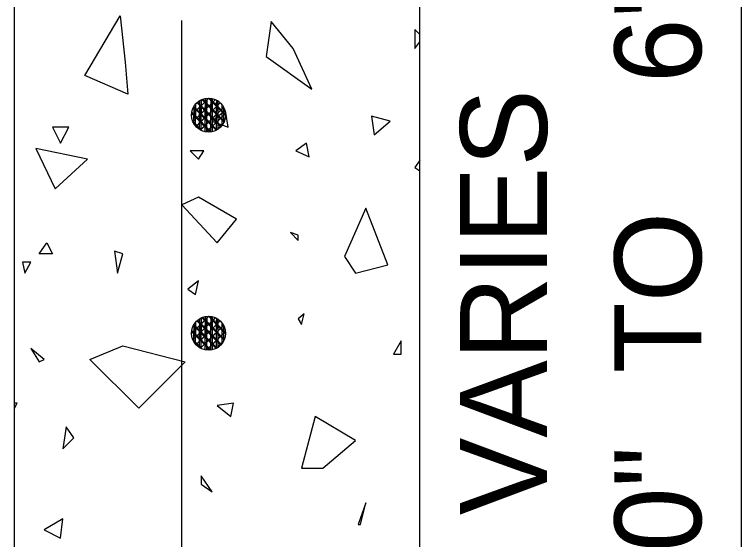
# Model space of a CAD drawing. Extents: x 8.6 to 15.9, y 6.4 to 16.6.
# Drawn here: x 11.677 to 12.179, y 12.084 to 12.447 of the extents above; entities that cross this region are included whole.
import ezdxf

# ---------------------------------------------------------------- set-up
doc = ezdxf.new("R2010")
doc.units = 0
for name, color, linetype in [('DETL-DIMS', 7, 'Continuous'), ('DETL-LINE', 7, 'Continuous'), ('DETL-NOTE', 7, 'Continuous'), ('DETL-PATT', 7, 'Continuous')]:
    doc.layers.add(name, color=color, linetype=linetype)

msp = doc.modelspace()

# ---------------------------------------------------------------- linework, layer by layer
at = {"layer": 'DETL-DIMS'}
msp.add_line((12.17919, 11.92421), (12.17919, 12.60906), dxfattribs=at)
at = {"layer": 'DETL-LINE'}
for p, q in [((11.95697, 9.51644), (11.95697, 12.84203)), ((11.67679, 9.84944), (11.67679, 12.60906)), ((11.79234, 11.96892), (11.79234, 12.44273)), ((11.8096, 12.38747), (11.80071, 12.37873)), ((11.81231, 12.38469), (11.80338, 12.37595)), ((11.80471, 12.37373), (11.80482, 12.38621)), ((11.81379, 12.37547), (11.80505, 12.38436)), ((11.80582, 12.37373), (11.80594, 12.38621)), ((11.81508, 12.38744), (11.80616, 12.37869)), ((11.81627, 12.37777), (11.80753, 12.38666)), ((11.81657, 12.37821), (11.80779, 12.3871)), ((11.8086, 12.37369), (11.80871, 12.38618)), ((11.81779, 12.38466), (11.8089, 12.37592)), ((11.80971, 12.37369), (11.80979, 12.38618)), ((11.81249, 12.37366), (11.8126, 12.38614)), ((11.82179, 12.37773), (11.81305, 12.38662)), ((11.82205, 12.37814), (11.81331, 12.38703)), ((11.8136, 12.37366), (11.81368, 12.38614)), ((11.81638, 12.37362), (11.81649, 12.3861)), ((11.81745, 12.37362), (11.81757, 12.3861)), ((11.80953, 12.38195), (11.80064, 12.37321)), ((11.8019, 12.36988), (11.80201, 12.38236)), ((11.81071, 12.37232), (11.80197, 12.38125)), ((11.81101, 12.37273), (11.80227, 12.38162)), ((11.80468, 12.36984), (11.80479, 12.38232)), ((11.81349, 12.37506), (11.80475, 12.38395)), ((11.80579, 12.36984), (11.8059, 12.38232)), ((11.81505, 12.38192), (11.80612, 12.37318)), ((11.81623, 12.37229), (11.80749, 12.38121)), ((11.81653, 12.37269), (11.80775, 12.38158)), ((11.80857, 12.36981), (11.80868, 12.38229)), ((11.80968, 12.36981), (11.80979, 12.38229)), ((11.81901, 12.37499), (11.81027, 12.38388)), ((11.81931, 12.37544), (11.81053, 12.38432)), ((11.82053, 12.38188), (11.81164, 12.37314)), ((11.81245, 12.36977), (11.81257, 12.38225)), ((11.81357, 12.36977), (11.81368, 12.38225)), ((11.81634, 12.36977), (11.81645, 12.38221)), ((11.81745, 12.36973), (11.81757, 12.38221)), ((11.80797, 12.36962), (11.79919, 12.37851)), ((11.80823, 12.37003), (11.79949, 12.37892)), ((11.81068, 12.36684), (11.80194, 12.37573)), ((11.81097, 12.36725), (11.80223, 12.37618)), ((11.81227, 12.37921), (11.80334, 12.37044)), ((11.81345, 12.36958), (11.80471, 12.37847)), ((11.81375, 12.36995), (11.80501, 12.37884)), ((11.81501, 12.37644), (11.80608, 12.36766)), ((11.81619, 12.36681), (11.80745, 12.37569)), ((11.81649, 12.36718), (11.80771, 12.3761)), ((11.80853, 12.36592), (11.80864, 12.3784)), ((11.81775, 12.37918), (11.80886, 12.3704)), ((11.80964, 12.36592), (11.80975, 12.3784)), ((11.81897, 12.36955), (11.81023, 12.37844)), ((11.81927, 12.36992), (11.81049, 12.37881)), ((11.82049, 12.3764), (11.8116, 12.36762)), ((11.81242, 12.36588), (11.81253, 12.37836)), ((11.81353, 12.36588), (11.81364, 12.37836)), ((11.8096, 12.23677), (11.80071, 12.22803)), ((11.81231, 12.23399), (11.80338, 12.22525)), ((11.80471, 12.22303), (11.80482, 12.23551)), ((11.81379, 12.22477), (11.80505, 12.23366)), ((11.80582, 12.22303), (11.80594, 12.23551)), ((11.81508, 12.23673), (11.80616, 12.22799)), ((11.81627, 12.22706), (11.80753, 12.23595)), ((11.81657, 12.22751), (11.80779, 12.2364)), ((11.8086, 12.22299), (11.80871, 12.23547)), ((11.81779, 12.23395), (11.8089, 12.22521)), ((11.80971, 12.22299), (11.80979, 12.23547)), ((11.81931, 12.22473), (11.81053, 12.23362)), ((11.81249, 12.22295), (11.8126, 12.23544)), ((11.82179, 12.22703), (11.81305, 12.23592)), ((11.82205, 12.22744), (11.81331, 12.23632)), ((11.8136, 12.22295), (11.81368, 12.23544)), ((11.81638, 12.22292), (11.81649, 12.2354)), ((11.81745, 12.22292), (11.81757, 12.2354)), ((11.80953, 12.23125), (11.80064, 12.22251)), ((11.8019, 12.21918), (11.80201, 12.23166)), ((11.81071, 12.22162), (11.80197, 12.23055)), ((11.81101, 12.22203), (11.80227, 12.23092)), ((11.80468, 12.21914), (11.80479, 12.23162)), ((11.81349, 12.22436), (11.80475, 12.23325)), ((11.80579, 12.21914), (11.8059, 12.23162)), ((11.81505, 12.23121), (11.80612, 12.22247)), ((11.81623, 12.22158), (11.80749, 12.23051)), ((11.81653, 12.22199), (11.80775, 12.23088)), ((11.80857, 12.2191), (11.80868, 12.23158)), ((11.80968, 12.2191), (11.80979, 12.23158)), ((11.81901, 12.22429), (11.81027, 12.23318)), ((11.82053, 12.23118), (11.81164, 12.22244)), ((11.81245, 12.21906), (11.81257, 12.23155)), ((11.81357, 12.21906), (11.81368, 12.23155)), ((11.81634, 12.21906), (11.81645, 12.23151)), ((11.81745, 12.21903), (11.81757, 12.23151)), ((11.80797, 12.21892), (11.79919, 12.22781)), ((11.80823, 12.21932), (11.79949, 12.22821)), ((11.81068, 12.21614), (11.80194, 12.22503)), ((11.81097, 12.21655), (11.80223, 12.22547)), ((11.81227, 12.22851), (11.80334, 12.21973)), ((11.81345, 12.21888), (11.80471, 12.22777)), ((11.81375, 12.21925), (11.80501, 12.22814)), ((11.81501, 12.22573), (11.80608, 12.21695)), ((11.81619, 12.2161), (11.80745, 12.22499)), ((11.81649, 12.21647), (11.80771, 12.2254)), ((11.80853, 12.21521), (11.80864, 12.22769)), ((11.81775, 12.22847), (11.80886, 12.21969)), ((11.80964, 12.21521), (11.80975, 12.22769)), ((11.81897, 12.21884), (11.81023, 12.22773)), ((11.81927, 12.21921), (11.81049, 12.2281)), ((11.82049, 12.22569), (11.8116, 12.21692)), ((11.81242, 12.21518), (11.81253, 12.22766)), ((11.81353, 12.21518), (11.81364, 12.22766))]:
    msp.add_line(p, q, dxfattribs=at)
for points in [[(11.80682, 12.38473), (11.79912, 12.37718)], [(11.80194, 12.37377), (11.80201, 12.38499)], [(11.80197, 12.37766), (11.80201, 12.38499)], [(11.80197, 12.38155), (11.80201, 12.38499)], [(11.81079, 12.37784), (11.80286, 12.38588)], [(11.80808, 12.38062), (11.80286, 12.38588)], [(11.80534, 12.3834), (11.80286, 12.38588)], [(11.81105, 12.37825), (11.80327, 12.38618)], [(11.80834, 12.38103), (11.80327, 12.38618)], [(11.8056, 12.38381), (11.80327, 12.38618)], [(11.81112, 12.38899), (11.80345, 12.38147)], [(11.80475, 12.37762), (11.80482, 12.38732)], [(11.80479, 12.38151), (11.80482, 12.38732)], [(11.80482, 12.3854), (11.80482, 12.38732)], [(11.80582, 12.37762), (11.80594, 12.38792)], [(11.80586, 12.38151), (11.80594, 12.38792)], [(11.8059, 12.3854), (11.80594, 12.38792)], [(11.81112, 12.38899), (11.80623, 12.38418)], [(11.81357, 12.38055), (11.80623, 12.38803)], [(11.81082, 12.38332), (11.80623, 12.38803)], [(11.80812, 12.3861), (11.80623, 12.38803)], [(11.81382, 12.38099), (11.80671, 12.38825)], [(11.81112, 12.38377), (11.80671, 12.38825)], [(11.80838, 12.38651), (11.80671, 12.38825)], [(11.80864, 12.37758), (11.80871, 12.38881)], [(11.80868, 12.38147), (11.80871, 12.38881)], [(11.80871, 12.38536), (11.80871, 12.38881)], [(11.81564, 12.38795), (11.80894, 12.3814)], [(11.80971, 12.37758), (11.80982, 12.38895)], [(11.80975, 12.38147), (11.80982, 12.38895)], [(11.80979, 12.38536), (11.80982, 12.38895)], [(11.81905, 12.38051), (11.81075, 12.38899)], [(11.81634, 12.38329), (11.81075, 12.38899)], [(11.8136, 12.38606), (11.81075, 12.38899)], [(11.81086, 12.38884), (11.81075, 12.38899)], [(11.81934, 12.38092), (11.81142, 12.38899)], [(11.8166, 12.38369), (11.81142, 12.38899)], [(11.8139, 12.38647), (11.81142, 12.38899)], [(11.81894, 12.38577), (11.81168, 12.37862)], [(11.81253, 12.37755), (11.8126, 12.38884)], [(11.81257, 12.38144), (11.8126, 12.38884)], [(11.8126, 12.38532), (11.8126, 12.38884)], [(11.8136, 12.37755), (11.81371, 12.38862)], [(11.81364, 12.38144), (11.81371, 12.38862)], [(11.81368, 12.38532), (11.81371, 12.38862)], [(11.81642, 12.37751), (11.81649, 12.38755)], [(11.81645, 12.3814), (11.81649, 12.38755)], [(11.81645, 12.38529), (11.81649, 12.38755)], [(11.81749, 12.37751), (11.8176, 12.38688)], [(11.81753, 12.3814), (11.8176, 12.38688)], [(11.81757, 12.38529), (11.8176, 12.38688)], [(11.80405, 12.38199), (11.79912, 12.37718)], [(11.80127, 12.37932), (11.79912, 12.37718)], [(11.80801, 12.3751), (11.80049, 12.38277)], [(11.80531, 12.37788), (11.80049, 12.38277)], [(11.80257, 12.38066), (11.80049, 12.38277)], [(11.80827, 12.37551), (11.80075, 12.38321)], [(11.80557, 12.37829), (11.80075, 12.38321)], [(11.80282, 12.38106), (11.80075, 12.38321)], [(11.80079, 12.37121), (11.8009, 12.38236)], [(11.80082, 12.37377), (11.8009, 12.38347)], [(11.80086, 12.37766), (11.8009, 12.38347)], [(11.8009, 12.38155), (11.8009, 12.38347)], [(11.82157, 12.3724), (11.81301, 12.38114)], [(11.82179, 12.37292), (11.81327, 12.38155)], [(11.82131, 12.38262), (11.81442, 12.37584)], [(11.8226, 12.37692), (11.81575, 12.38384)], [(11.8226, 12.37758), (11.81605, 12.38425)], [(11.8226, 12.37692), (11.81849, 12.3811)], [(11.8226, 12.37758), (11.81879, 12.38147)], [(11.82023, 12.37018), (11.82034, 12.38218)], [(11.82027, 12.37362), (11.82034, 12.38418)], [(11.82031, 12.37751), (11.82034, 12.38418)], [(11.82034, 12.3814), (11.82034, 12.38418)], [(11.82134, 12.37358), (11.82145, 12.38236)], [(11.82134, 12.37192), (11.82142, 12.38218)], [(11.82138, 12.37747), (11.82145, 12.38236)], [(11.82142, 12.38136), (11.82145, 12.38236)], [(11.80523, 12.37236), (11.79919, 12.37851)], [(11.80253, 12.37514), (11.79919, 12.37851)], [(11.79979, 12.37792), (11.79919, 12.37851)], [(11.80549, 12.37281), (11.79927, 12.37918)], [(11.80279, 12.37558), (11.79927, 12.37918)], [(11.80008, 12.37836), (11.79927, 12.37918)], [(11.80675, 12.37925), (11.80005, 12.37266)], [(11.80397, 12.37655), (11.80005, 12.37266)], [(11.80079, 12.37121), (11.80086, 12.37847)], [(11.80079, 12.37121), (11.80082, 12.37458)], [(11.8019, 12.36969), (11.80197, 12.37847)], [(11.8019, 12.36969), (11.80194, 12.37458)], [(11.80949, 12.37647), (11.80219, 12.36932)], [(11.80464, 12.36729), (11.80475, 12.37844)], [(11.80464, 12.36729), (11.80471, 12.37455)], [(11.80575, 12.36666), (11.80586, 12.37844)], [(11.80575, 12.36666), (11.80582, 12.37455)], [(11.80853, 12.36573), (11.8086, 12.37451)], [(11.80964, 12.36555), (11.80971, 12.37451)], [(11.81242, 12.36562), (11.81249, 12.37447)], [(11.81938, 12.3691), (11.81294, 12.37566)], [(11.81968, 12.36951), (11.81323, 12.37606)], [(11.81353, 12.36581), (11.8136, 12.37447)], [(11.82253, 12.3784), (11.81438, 12.37036)], [(11.82157, 12.3724), (11.81571, 12.37836)], [(11.82179, 12.37292), (11.81601, 12.37877)], [(11.81631, 12.36684), (11.81642, 12.37832)], [(11.81631, 12.36684), (11.81638, 12.37444)], [(11.82253, 12.3784), (11.81716, 12.37306)], [(11.81742, 12.36751), (11.81753, 12.37832)], [(11.81742, 12.36751), (11.81749, 12.37444)], [(11.82023, 12.37018), (11.82031, 12.37829)], [(11.82023, 12.37018), (11.82027, 12.3744)], [(11.82134, 12.37192), (11.82142, 12.37829)], [(11.82134, 12.37192), (11.82138, 12.3744)], [(11.80634, 12.3664), (11.79994, 12.37295)], [(11.80545, 12.36729), (11.79994, 12.37295)], [(11.80271, 12.37006), (11.79994, 12.37295)], [(11.80005, 12.37284), (11.79994, 12.37295)], [(11.80119, 12.37381), (11.80005, 12.37266)], [(11.80508, 12.36699), (11.80053, 12.37162)], [(11.80508, 12.36699), (11.80053, 12.37162)], [(11.80245, 12.36969), (11.80053, 12.37162)], [(11.80508, 12.36699), (11.8019, 12.37025)], [(11.80671, 12.37377), (11.80219, 12.36932)], [(11.80394, 12.37103), (11.80219, 12.36932)], [(11.80634, 12.3664), (11.80219, 12.37066)], [(11.81197, 12.36555), (11.80468, 12.37295)], [(11.81253, 12.36562), (11.80497, 12.3734)], [(11.81223, 12.37369), (11.80531, 12.36688)], [(11.80945, 12.37099), (11.80531, 12.36688)], [(11.81197, 12.36555), (11.80738, 12.37018)], [(11.81253, 12.36562), (11.80768, 12.37062)], [(11.81771, 12.37366), (11.80949, 12.36558)], [(11.81494, 12.37092), (11.80949, 12.36558)], [(11.81623, 12.36677), (11.81016, 12.37292)], [(11.81664, 12.36703), (11.81045, 12.37332)], [(11.82119, 12.37162), (11.81631, 12.36681)], [(11.82042, 12.37088), (11.81631, 12.36681)], [(11.82119, 12.37162), (11.81708, 12.36758)], [(11.82119, 12.37162), (11.81986, 12.37029)], [(11.80508, 12.36699), (11.8046, 12.36747)], [(11.80634, 12.3664), (11.8049, 12.36788)], [(11.80668, 12.36825), (11.80531, 12.36688)], [(11.81216, 12.36821), (11.80949, 12.36558)], [(11.81764, 12.36814), (11.81631, 12.36681)], [(11.80682, 12.23403), (11.79912, 12.22647)], [(11.80194, 12.22306), (11.80201, 12.23429)], [(11.80197, 12.22695), (11.80201, 12.23429)], [(11.80197, 12.23084), (11.80201, 12.23429)], [(11.81079, 12.22714), (11.80286, 12.23518)], [(11.80808, 12.22992), (11.80286, 12.23518)], [(11.80534, 12.23269), (11.80286, 12.23518)], [(11.81105, 12.22755), (11.80327, 12.23547)], [(11.80834, 12.23032), (11.80327, 12.23547)], [(11.8056, 12.2331), (11.80327, 12.23547)], [(11.81112, 12.23829), (11.80345, 12.23077)], [(11.80475, 12.22692), (11.80482, 12.23662)], [(11.80479, 12.23081), (11.80482, 12.23662)], [(11.80482, 12.23469), (11.80482, 12.23662)], [(11.80582, 12.22692), (11.80594, 12.23721)], [(11.80586, 12.23081), (11.80594, 12.23721)], [(11.8059, 12.23469), (11.80594, 12.23721)], [(11.81112, 12.23829), (11.80623, 12.23347)], [(11.81357, 12.22984), (11.80623, 12.23732)], [(11.81082, 12.23262), (11.80623, 12.23732)], [(11.80812, 12.2354), (11.80623, 12.23732)], [(11.81382, 12.23029), (11.80671, 12.23755)], [(11.81112, 12.23306), (11.80671, 12.23755)], [(11.80838, 12.23581), (11.80671, 12.23755)], [(11.80864, 12.22688), (11.80871, 12.2381)], [(11.80868, 12.23077), (11.80871, 12.2381)], [(11.80871, 12.23466), (11.80871, 12.2381)], [(11.81564, 12.23725), (11.80894, 12.23069)], [(11.80971, 12.22688), (11.80982, 12.23825)], [(11.80975, 12.23077), (11.80982, 12.23825)], [(11.80979, 12.23466), (11.80982, 12.23825)], [(11.81905, 12.22981), (11.81075, 12.23829)], [(11.81634, 12.23258), (11.81075, 12.23829)], [(11.8136, 12.23536), (11.81075, 12.23829)], [(11.81086, 12.23814), (11.81075, 12.23829)], [(11.81934, 12.23021), (11.81142, 12.23829)], [(11.8166, 12.23299), (11.81142, 12.23829)], [(11.8139, 12.23577), (11.81142, 12.23829)], [(11.81894, 12.23506), (11.81168, 12.22792)], [(11.81253, 12.22684), (11.8126, 12.23814)], [(11.81257, 12.23073), (11.8126, 12.23814)], [(11.8126, 12.23462), (11.8126, 12.23814)], [(11.8136, 12.22684), (11.81371, 12.23792)], [(11.81364, 12.23073), (11.81371, 12.23792)], [(11.81368, 12.23462), (11.81371, 12.23792)], [(11.81642, 12.22681), (11.81649, 12.23684)], [(11.81645, 12.23069), (11.81649, 12.23684)], [(11.81645, 12.23458), (11.81649, 12.23684)], [(11.81749, 12.22681), (11.8176, 12.23618)], [(11.81753, 12.23069), (11.8176, 12.23618)], [(11.81757, 12.23458), (11.8176, 12.23618)], [(11.80405, 12.23129), (11.79912, 12.22647)], [(11.80127, 12.22862), (11.79912, 12.22647)], [(11.80801, 12.2244), (11.80049, 12.23206)], [(11.80531, 12.22718), (11.80049, 12.23206)], [(11.80257, 12.22995), (11.80049, 12.23206)], [(11.80827, 12.22481), (11.80075, 12.23251)], [(11.80557, 12.22758), (11.80075, 12.23251)], [(11.80282, 12.23036), (11.80075, 12.23251)], [(11.80079, 12.22051), (11.8009, 12.23166)], [(11.80082, 12.22306), (11.8009, 12.23277)], [(11.80086, 12.22695), (11.8009, 12.23277)], [(11.8009, 12.23084), (11.8009, 12.23277)], [(11.82157, 12.22169), (11.81301, 12.23044)], [(11.82179, 12.22221), (11.81327, 12.23084)], [(11.82131, 12.23192), (11.81442, 12.22514)], [(11.8226, 12.22621), (11.81575, 12.23314)], [(11.8226, 12.22688), (11.81605, 12.23355)], [(11.8226, 12.22621), (11.81849, 12.2304)], [(11.8226, 12.22688), (11.81879, 12.23077)], [(11.82023, 12.21947), (11.82034, 12.23147)], [(11.82027, 12.22292), (11.82034, 12.23347)], [(11.82031, 12.22681), (11.82034, 12.23347)], [(11.82034, 12.23069), (11.82034, 12.23347)], [(11.82134, 12.22288), (11.82145, 12.23166)], [(11.82134, 12.22121), (11.82142, 12.23147)], [(11.82138, 12.22677), (11.82145, 12.23166)], [(11.82142, 12.23066), (11.82145, 12.23166)], [(11.80523, 12.22166), (11.79919, 12.22781)], [(11.80253, 12.22444), (11.79919, 12.22781)], [(11.79979, 12.22721), (11.79919, 12.22781)], [(11.80549, 12.2221), (11.79927, 12.22847)], [(11.80279, 12.22488), (11.79927, 12.22847)], [(11.80008, 12.22766), (11.79927, 12.22847)], [(11.80675, 12.22855), (11.80005, 12.22195)], [(11.80397, 12.22584), (11.80005, 12.22195)], [(11.80079, 12.22051), (11.80086, 12.22777)], [(11.80079, 12.22051), (11.80082, 12.22388)], [(11.8019, 12.21899), (11.80197, 12.22777)], [(11.8019, 12.21899), (11.80194, 12.22388)], [(11.80949, 12.22577), (11.80219, 12.21862)], [(11.80464, 12.21658), (11.80475, 12.22773)], [(11.80464, 12.21658), (11.80471, 12.22384)], [(11.80575, 12.21595), (11.80586, 12.22773)], [(11.80575, 12.21595), (11.80582, 12.22384)], [(11.80853, 12.21503), (11.8086, 12.22381)], [(11.80964, 12.21484), (11.80971, 12.22381)], [(11.81242, 12.21492), (11.81249, 12.22377)], [(11.81938, 12.2184), (11.81294, 12.22495)], [(11.81968, 12.21881), (11.81323, 12.22536)], [(11.81353, 12.2151), (11.8136, 12.22377)], [(11.82253, 12.22769), (11.81438, 12.21966)], [(11.82157, 12.22169), (11.81571, 12.22766)], [(11.82179, 12.22221), (11.81601, 12.22806)], [(11.81631, 12.21614), (11.81642, 12.22762)], [(11.81631, 12.21614), (11.81638, 12.22373)], [(11.82253, 12.22769), (11.81716, 12.22236)], [(11.81742, 12.21681), (11.81753, 12.22762)], [(11.81742, 12.21681), (11.81749, 12.22373)], [(11.82023, 12.21947), (11.82031, 12.22758)], [(11.82023, 12.21947), (11.82027, 12.22369)], [(11.82134, 12.22121), (11.82142, 12.22758)], [(11.82134, 12.22121), (11.82138, 12.22369)], [(11.80634, 12.21569), (11.79994, 12.22225)], [(11.80545, 12.21658), (11.79994, 12.22225)], [(11.80271, 12.21936), (11.79994, 12.22225)], [(11.80005, 12.22214), (11.79994, 12.22225)], [(11.80119, 12.2231), (11.80005, 12.22195)], [(11.80508, 12.21629), (11.80053, 12.22092)], [(11.80508, 12.21629), (11.80053, 12.22092)], [(11.80245, 12.21899), (11.80053, 12.22092)], [(11.80508, 12.21629), (11.8019, 12.21955)], [(11.80671, 12.22306), (11.80219, 12.21862)], [(11.80394, 12.22032), (11.80219, 12.21862)], [(11.80634, 12.21569), (11.80219, 12.21995)], [(11.81197, 12.21484), (11.80468, 12.22225)], [(11.81253, 12.21492), (11.80497, 12.22269)], [(11.81223, 12.22299), (11.80531, 12.21618)], [(11.80945, 12.22029), (11.80531, 12.21618)], [(11.81197, 12.21484), (11.80738, 12.21947)], [(11.81253, 12.21492), (11.80768, 12.21992)], [(11.81771, 12.22295), (11.80949, 12.21488)], [(11.81494, 12.22021), (11.80949, 12.21488)], [(11.81623, 12.21606), (11.81016, 12.22221)], [(11.81664, 12.21632), (11.81045, 12.22262)], [(11.82119, 12.22092), (11.81631, 12.2161)], [(11.82042, 12.22018), (11.81631, 12.2161)], [(11.82119, 12.22092), (11.81708, 12.21688)], [(11.82119, 12.22092), (11.81986, 12.21958)], [(11.80508, 12.21629), (11.8046, 12.21677)], [(11.80634, 12.21569), (11.8049, 12.21718)], [(11.80668, 12.21755), (11.80531, 12.21618)], [(11.81216, 12.21751), (11.80949, 12.21488)], [(11.81764, 12.21744), (11.81631, 12.2161)]]:
    msp.add_lwpolyline(points, dxfattribs=at)
for centre in [(11.81086, 12.37724), (11.81086, 12.22654)]:
    msp.add_circle(centre, 0.01177, dxfattribs=at)
at = {"layer": 'DETL-PATT'}
for points in [[(11.75334, 12.41384), (11.75512, 12.39162), (11.72534, 12.40451), (11.74979, 12.44584)], [(11.85423, 12.44184), (11.85068, 12.41784), (11.88223, 12.39518), (11.86934, 12.42318)], [(11.82268, 12.38051), (11.81334, 12.37295), (11.82445, 12.36895)], [(11.92357, 12.37651), (11.92534, 12.36362), (11.93645, 12.37295)], [(11.70312, 12.36895), (11.70845, 12.35784), (11.71423, 12.36895)], [(11.69157, 12.35429), (11.7049, 12.32629), (11.72712, 12.34673)], [(11.87112, 12.35251), (11.88045, 12.34851), (11.87868, 12.35784)], [(11.79823, 12.35251), (11.80401, 12.34673), (11.80757, 12.35251)], [(11.79245, 12.31518), (11.8169, 12.28895), (11.83023, 12.3054), (11.80401, 12.32051)], [(11.91245, 12.26806), (11.93468, 12.27384), (11.91957, 12.31295), (11.9049, 12.27962)], [(11.8729, 12.29429), (11.86757, 12.29606), (11.8729, 12.29073)], [(11.69912, 12.28895), (11.70312, 12.2814), (11.69379, 12.2814)], [(11.74579, 12.28318), (11.74801, 12.26806), (11.75157, 12.2814)], [(11.68223, 12.27562), (11.68401, 12.26806), (11.68801, 12.27562)], [(11.79645, 12.25695), (11.80179, 12.2534), (11.80401, 12.26273)], [(11.8769, 12.24006), (11.8729, 12.23651), (11.87512, 12.23251)], [(11.94401, 12.2214), (11.93868, 12.21206), (11.94401, 12.21206)], [(11.69379, 12.20673), (11.69734, 12.20851), (11.68801, 12.21606)], [(11.75157, 12.21784), (11.79468, 12.20673), (11.76268, 12.17473), (11.7289, 12.20851)], [(11.8169, 12.17651), (11.82623, 12.16895), (11.82801, 12.17829)], [(11.88979, 12.1334), (11.91245, 12.15251), (11.88445, 12.16895), (11.87512, 12.1334)], [(11.71245, 12.16184), (11.71023, 12.14673), (11.71779, 12.15429)], [(11.80579, 12.12806), (11.80579, 12.12229), (11.81334, 12.11695)], [(11.91423, 12.09429), (11.91601, 12.09429), (11.91957, 12.1094)], [(11.69734, 12.09073), (11.70845, 12.08495), (11.71023, 12.09829)]]:
    msp.add_lwpolyline(points, close=True, dxfattribs=at)
for points in [[(11.95697, 12.43288), (11.95334, 12.43651), (11.95334, 12.42318), (11.95697, 12.42792)], [(11.95697, 12.34618), (11.95334, 12.34095), (11.95697, 12.33873)], [(11.67679, 12.17466), (11.67868, 12.17829), (11.67679, 12.17829)]]:
    msp.add_lwpolyline(points, dxfattribs=at)

# ---------------------------------------------------------------- texts
at = {"layer": 'DETL-NOTE'}
for s, p in [('6\'-0"', (12.15142, 12.3994)), ('VARIES', (12.04475, 12.10088)), ('TO', (12.15142, 12.19895)), ('1\'-0"', (12.15142, 11.98873))]:
    msp.add_text(s, height=0.06, rotation=90, dxfattribs=at).set_placement(p)

doc.saveas('drawing.dxf')
